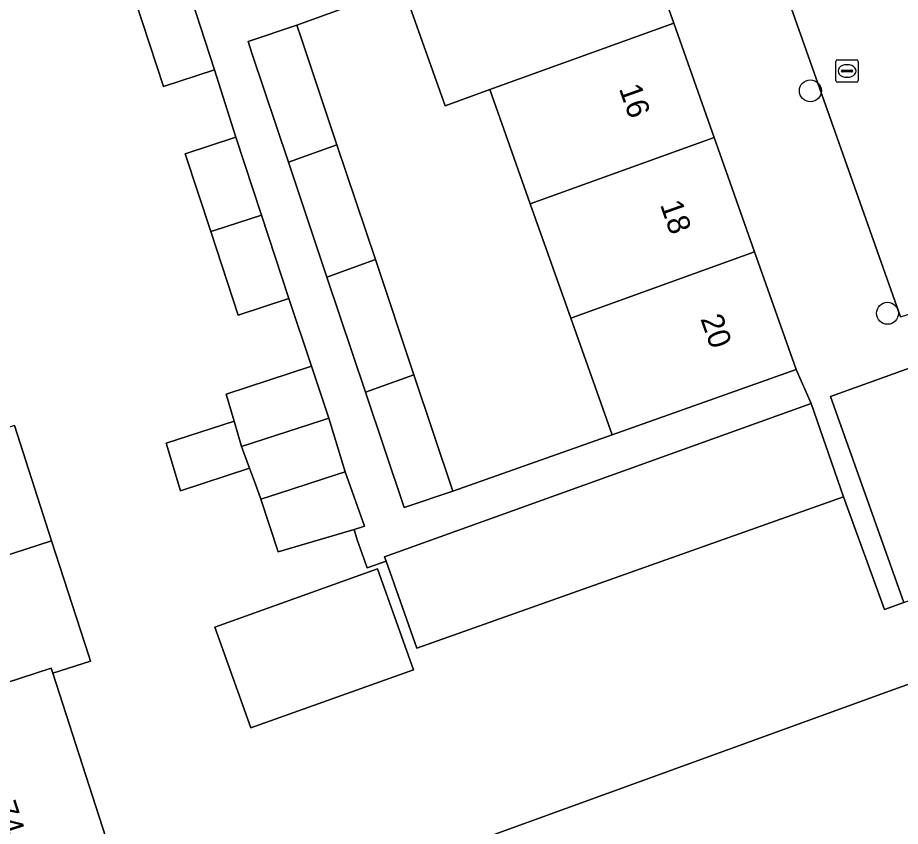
# Model space of a CAD drawing. Extents: x 159371 to 159986, y 382987 to 383597.
# Drawn here: x 159661.2 to 159700.54, y 383131.92 to 383167.94 of the extents above; entities that cross this region are included whole.
import ezdxf

# ---------------------------------------------------------------- set-up
doc = ezdxf.new("R2010")
doc.units = 0
for name, color, linetype in [('IMGEO_Boom', 7, 'Continuous'), ('IMGEO_Erf', 7, 'Continuous'), ('IMGEO_Kolk', 7, 'Continuous'), ('IMGEO_Muur', 7, 'Continuous'), ('IMGEO_Pand', 7, 'Continuous'), ('IMGEO_Pand_nummerreeks', 7, 'Continuous'), ('IMGEO_Parkeervlak_open', 7, 'Continuous'), ('IMGEO_Rijbaan_lokaal_open', 7, 'Continuous'), ('IMGEO_Voetpad_open', 7, 'Continuous')]:
    doc.layers.add(name, color=color, linetype=linetype)

msp = doc.modelspace()

# ---------------------------------------------------------------- linework, layer by layer
at = {"layer": 'IMGEO_Boom'}
for centre in [(159696.527, 383164.685), (159699.963, 383154.774)]:
    msp.add_circle(centre, 0.489, dxfattribs=at)
at = {"layer": 'IMGEO_Erf'}
for points in [[(159684.045, 383159.653), (159682.244, 383164.74), (159680.246, 383164.019), (159678.366, 383169.328), (159673.642, 383167.613), (159673.83, 383167.05), (159675.427, 383162.28), (159677.142, 383157.163), (159678.86, 383152.034), (159680.595, 383146.854), (159687.69, 383149.36), (159685.85, 383154.557)], [(159677.235, 383143.385), (159678.838, 383138.891), (159671.585, 383136.304), (159669.982, 383140.798)]]:
    msp.add_lwpolyline(points, close=True, dxfattribs=at)
for points in [[(159700.696, 383141.898), (159699.831, 383141.577), (159698.005, 383146.592), (159678.991, 383139.86), (159677.618, 383143.736), (159676.779, 383143.437), (159676.335, 383144.683), (159676.195, 383145.151), (159672.812, 383144.142), (159672.033, 383146.496), (159671.796, 383147.16), (159671.534, 383147.871), (159668.449, 383146.867), (159667.817, 383148.988), (159670.844, 383149.972), (159670.484, 383151.179), (159674.295, 383152.417), (159673.283, 383155.434), (159671.022, 383154.694), (159669.806, 383158.411), (159668.669, 383161.883), (159670.929, 383162.623), (159669.976, 383165.62), (159667.691, 383164.872), (159666.447, 383168.674)], [(159661.057, 383149.776), (159662.714, 383144.643), (159664.37, 383139.511), (159664.444, 383139.282), (159662.767, 383138.741), (159666.005, 383128.71)], [(159669.71, 383126.945), (159699.879, 383137.876), (159704.579, 383139.579)]]:
    msp.add_lwpolyline(points, dxfattribs=at)
at = {"layer": 'IMGEO_Kolk'}
for p, q in [((159697.659, 383165.14), (159697.659, 383165.992)), ((159697.734, 383166.066), (159698.586, 383166.066)), ((159698.147, 383165.846), (159698.172, 383165.846)), ((159698.66, 383165.992), (159698.66, 383165.14)), ((159697.918, 383165.56), (159697.918, 383165.572)), ((159698.356, 383165.523), (159697.958, 383165.523)), ((159697.961, 383165.609), (159698.359, 383165.609)), ((159698.402, 383165.572), (159698.402, 383165.56)), ((159698.586, 383165.066), (159697.734, 383165.066)), ((159698.17, 383165.286), (159698.145, 383165.286))]:
    msp.add_line(p, q, dxfattribs=at)
for points in [[(159697.659, 383165.14), (159697.659, 383165.992)], [(159697.734, 383166.066), (159698.586, 383166.066)], [(159698.66, 383165.992), (159698.66, 383165.14)], [(159698.586, 383165.066), (159697.734, 383165.066)]]:
    msp.add_lwpolyline(points, dxfattribs=at)
for centre, radius, start, end in [((159697.736, 383165.99), 0.0765, 91.552, 178.448), ((159697.736, 383165.99), 0.0765, 91.552, 178.448), ((159698.584, 383165.99), 0.0765, 1.552, 88.448), ((159698.584, 383165.99), 0.0765, 1.552, 88.448), ((159697.958, 383165.569), 0.0403, 85.8775, 175.7526), ((159697.955, 383165.559), 0.0366, 178.938, 274.7102), ((159698.359, 383165.566), 0.043, 264.8664, 352.4533), ((159698.363, 383165.571), 0.0386, 1.7309, 96.639), ((159697.736, 383165.142), 0.0765, 181.552, 268.448), ((159697.736, 383165.142), 0.0765, 181.552, 268.448), ((159698.584, 383165.142), 0.0765, 271.552, 358.448), ((159698.584, 383165.142), 0.0765, 271.552, 358.448)]:
    msp.add_arc(centre, radius, start, end, dxfattribs=at)
for centre, major_axis, ratio, start_param, end_param in [((159698.146, 383165.566), (-0.387, 0.002), 0.722429, 4.712389, 7.853982), ((159698.171, 383165.566), (-0.39, 0.002), 0.717154, 1.570796, 4.712389)]:
    msp.add_ellipse(centre, major_axis=major_axis, ratio=ratio, start_param=start_param, end_param=end_param, dxfattribs=at)
at = {"layer": 'IMGEO_Muur'}
msp.add_lwpolyline([(159698.005, 383146.592), (159699.831, 383141.577), (159700.696, 383141.898)], dxfattribs=at)
at = {"layer": 'IMGEO_Pand'}
for points in [[(159688.576, 383172.943), (159686.917, 383172.356), (159680.368, 383170.037), (159678.366, 383169.328), (159680.246, 383164.019), (159682.244, 383164.74), (159690.434, 383167.695)], [(159668.733, 383169.416), (159666.447, 383168.674), (159667.691, 383164.872), (159669.976, 383165.62)], [(159673.83, 383167.05), (159673.642, 383167.613), (159671.464, 383166.883), (159671.652, 383166.32), (159673.266, 383161.501), (159675.427, 383162.28)], [(159690.434, 383167.695), (159682.244, 383164.74), (159684.045, 383159.653), (159692.236, 383162.608)], [(159670.929, 383162.623), (159668.669, 383161.883), (159669.806, 383158.411), (159669.954, 383158.459), (159672.068, 383159.145)], [(159694.04, 383157.513), (159692.236, 383162.608), (159684.045, 383159.653), (159685.85, 383154.557)], [(159673.266, 383161.501), (159674.98, 383156.383), (159677.142, 383157.163), (159675.427, 383162.28)], [(159672.068, 383159.145), (159669.954, 383158.459), (159669.806, 383158.411), (159671.022, 383154.694), (159673.283, 383155.434)], [(159694.04, 383157.513), (159685.85, 383154.557), (159687.69, 383149.36), (159695.898, 383152.266)], [(159676.698, 383151.254), (159678.86, 383152.034), (159677.142, 383157.163), (159674.98, 383156.383)], [(159674.295, 383152.417), (159670.484, 383151.179), (159670.844, 383149.972), (159671.18, 383148.844), (159674.748, 383150.003), (159675.06, 383150.104)], [(159676.698, 383151.254), (159678.417, 383146.124), (159680.595, 383146.854), (159678.86, 383152.034)], [(159698.005, 383146.592), (159696.555, 383150.754), (159677.552, 383143.921), (159677.618, 383143.736), (159678.991, 383139.86)], [(159675.06, 383150.104), (159674.748, 383150.003), (159671.18, 383148.844), (159671.534, 383147.871), (159671.796, 383147.16), (159672.033, 383146.496), (159672.818, 383146.751), (159675.462, 383147.609), (159675.793, 383147.717)], [(159652.658, 383147.049), (159654.315, 383141.917), (159662.714, 383144.643), (159661.057, 383149.776)], [(159671.18, 383148.844), (159670.844, 383149.972), (159667.817, 383148.988), (159668.449, 383146.867), (159671.534, 383147.871)], [(159675.793, 383147.717), (159675.462, 383147.609), (159672.818, 383146.751), (159672.033, 383146.496), (159672.812, 383144.142), (159676.195, 383145.151), (159676.528, 383145.25), (159676.653, 383145.288)], [(159662.714, 383144.643), (159654.315, 383141.917), (159655.885, 383137.052), (159655.971, 383136.784), (159662.694, 383138.967), (159662.767, 383138.741), (159664.444, 383139.282), (159664.37, 383139.511)], [(159667.794, 383123.344), (159669.201, 383123.801), (159671.247, 383118.076), (159709.84, 383132.115), (159705.514, 383143.666), (159703.379, 383142.892), (159704.579, 383139.579), (159699.879, 383137.876), (159669.71, 383126.945), (159669.098, 383128.842), (159668.061, 383129.373), (159666.005, 383128.71)], [(159677.235, 383143.385), (159669.982, 383140.798), (159671.585, 383136.304), (159678.838, 383138.891)], [(159662.767, 383138.741), (159662.694, 383138.967), (159655.971, 383136.784), (159655.885, 383137.052), (159654.204, 383136.509), (159654.291, 383136.239), (159659.423, 383120.624), (159667.794, 383123.344), (159666.005, 383128.71)]]:
    msp.add_lwpolyline(points, close=True, dxfattribs=at)
at = {"layer": 'IMGEO_Parkeervlak_open'}
msp.add_lwpolyline([(159705.514, 383143.666), (159702.301, 383152.82), (159697.424, 383151.066), (159700.696, 383141.898), (159703.379, 383142.892)], close=True, dxfattribs=at)
at = {"layer": 'IMGEO_Rijbaan_lokaal_open'}
msp.add_lwpolyline([(159693.603, 383175.063), (159693.704, 383174.782), (159693.435, 383174.689), (159700.541, 383154.623), (159702.376, 383155.2), (159709.858, 383134.615), (159710.636, 383132.475), (159713.607, 383133.562), (159712.83, 383135.72), (159705.026, 383157.403), (159705.773, 383157.67), (159698.957, 383176.699), (159698.668, 383176.596), (159698.578, 383176.847)], close=True, dxfattribs=at)
at = {"layer": 'IMGEO_Voetpad_open'}
for points in [[(159700.541, 383154.623), (159693.435, 383174.689)], [(159688.576, 383172.943), (159690.434, 383167.695), (159692.236, 383162.608), (159694.04, 383157.513), (159695.898, 383152.266), (159696.555, 383150.754), (159698.005, 383146.592), (159699.831, 383141.577), (159700.696, 383141.898), (159697.424, 383151.066), (159702.301, 383152.82)], [(159668.733, 383169.416), (159669.976, 383165.62), (159670.929, 383162.623), (159672.068, 383159.145), (159673.283, 383155.434), (159674.295, 383152.417), (159675.06, 383150.104), (159675.793, 383147.717), (159676.653, 383145.288), (159676.528, 383145.25), (159676.195, 383145.151), (159676.335, 383144.683), (159676.779, 383143.437), (159677.618, 383143.736), (159677.552, 383143.921), (159696.555, 383150.754), (159695.898, 383152.266), (159687.69, 383149.36), (159680.595, 383146.854), (159678.417, 383146.124), (159676.698, 383151.254), (159674.98, 383156.383), (159673.266, 383161.501), (159671.652, 383166.32), (159671.464, 383166.883), (159673.642, 383167.613), (159678.366, 383169.328)]]:
    msp.add_lwpolyline(points, dxfattribs=at)

# ---------------------------------------------------------------- texts
at = {"layer": 'IMGEO_Pand_nummerreeks'}
for s, rotation, p in [('16', 289.4997, (159687.984, 383164.787)), ('18', 289.4997, (159689.816, 383159.615)), ('20', 289.4997, (159691.616, 383154.532)), ('74-74A', 287.8875, (159660.127, 383132.873))]:
    msp.add_text(s, height=1, rotation=rotation, dxfattribs=at).set_placement(p)

doc.saveas('drawing.dxf')
